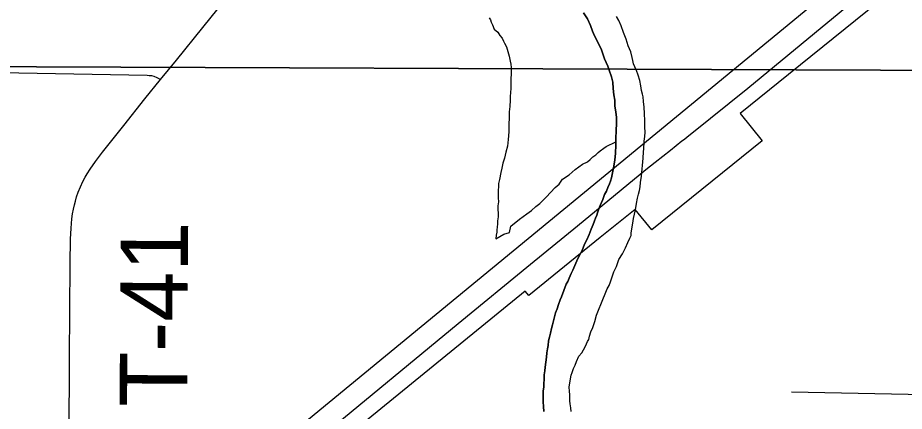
# Model space of a CAD drawing. Extents: x 0 to 34, y 0 to 22.
# Drawn here: x 4.659 to 5.405, y 19.15 to 19.482 of the extents above; entities that cross this region are included whole.
import ezdxf

# ---------------------------------------------------------------- set-up
doc = ezdxf.new("R2010")
doc.units = 0
for name, color, linetype in [('Default', 7, 'Continuous'), ('GM_X_City_Street', 7, 'Continuous'), ('GM_X_Major_River', 7, 'Continuous'), ('GM_X_Minor_River', 7, 'Continuous'), ('GM_X_Section', 7, 'Continuous'), ('GM_X_Township_Road', 7, 'Continuous'), ('GM_X_Township_Road_Text', 7, 'Continuous'), ('GM_X_US_Route', 7, 'Continuous')]:
    doc.layers.add(name, color=color, linetype=linetype)

msp = doc.modelspace()

# ---------------------------------------------------------------- linework, layer by layer
at = {"layer": 'Default'}
msp.add_lwpolyline([(5.44921, 19.54848), (5.30756, 19.4339), (5.26689, 19.40102), (5.28537, 19.37819), (5.19255, 19.3031), (5.1786, 19.32035), (5.14895, 19.29666), (5.08886, 19.24777), (5.08586, 19.25144), (4.91287, 19.11021)], dxfattribs=at)
at = {"layer": 'GM_X_City_Street'}
msp.add_line((5.31011, 19.16656), (5.45108, 19.16403), dxfattribs=at)
at = {"layer": 'GM_X_Major_River'}
for points in [[(5.1383, 19.48087), (5.14081, 19.47511), (5.1426, 19.4705), (5.1444, 19.46666), (5.14982, 19.45551), (5.15123, 19.4513), (5.15264, 19.44708), (5.15409, 19.44401), (5.15553, 19.44093), (5.15658, 19.43749), (5.15872, 19.43212), (5.15975, 19.42754), (5.15999, 19.42221), (5.16062, 19.41688), (5.16126, 19.41231), (5.16152, 19.40737), (5.16215, 19.40241), (5.1628, 19.39784), (5.16268, 19.39291), (5.16251, 19.38645), (5.16236, 19.38038), (5.16222, 19.37469), (5.16204, 19.36748), (5.16152, 19.36217), (5.16063, 19.35688), (5.15935, 19.35122), (5.15849, 19.34706), (5.15765, 19.34404), (5.15683, 19.34179), (5.15562, 19.33878), (5.1544, 19.33577), (5.15281, 19.33277), (5.15118, 19.32864), (5.14916, 19.32375), (5.14755, 19.32), (5.14672, 19.31736), (5.1463, 19.31547), (5.14509, 19.31284), (5.14427, 19.31059), (5.14306, 19.30758), (5.14144, 19.30382), (5.13981, 19.29931), (5.1378, 19.2948), (5.13581, 19.29105), (5.13377, 19.28579), (5.13138, 19.28129), (5.12938, 19.27716), (5.12775, 19.27302), (5.12614, 19.26927), (5.12455, 19.26627), (5.12293, 19.26252), (5.12172, 19.25951), (5.12052, 19.25726), (5.11646, 19.24673), (5.11525, 19.2441), (5.11402, 19.24034), (5.11278, 19.23657), (5.11156, 19.23318), (5.11071, 19.22978), (5.10987, 19.22639), (5.10903, 19.22299), (5.10819, 19.21997), (5.10734, 19.2162), (5.10649, 19.2128), (5.10566, 19.20978), (5.10517, 19.20562), (5.10472, 19.20297), (5.10426, 19.19956), (5.10378, 19.19578), (5.1033, 19.19161), (5.10282, 19.18745), (5.10236, 19.18442), (5.10189, 19.18102), (5.10183, 19.17836), (5.10178, 19.17646), (5.10172, 19.17419), (5.10164, 19.17077), (5.10117, 19.16736), (5.10107, 19.16319), (5.10094, 19.15825), (5.10123, 19.15445), (5.1015, 19.15026)], [(5.1015, 19.15026), (5.10123, 19.15445), (5.10094, 19.15825), (5.10107, 19.16319), (5.10117, 19.16736), (5.10164, 19.17077), (5.10172, 19.17419), (5.10178, 19.17646), (5.10183, 19.17836), (5.10189, 19.18102), (5.10236, 19.18442), (5.10282, 19.18745), (5.1033, 19.19161), (5.10378, 19.19578), (5.10426, 19.19956), (5.10472, 19.20297), (5.10517, 19.20562), (5.10566, 19.20978), (5.10649, 19.2128), (5.10734, 19.2162), (5.10819, 19.21997), (5.10903, 19.22299), (5.10987, 19.22639), (5.11071, 19.22978), (5.11156, 19.23318), (5.11278, 19.23657), (5.11402, 19.24034), (5.11525, 19.2441), (5.11646, 19.24673), (5.12052, 19.25726), (5.12172, 19.25951), (5.12293, 19.26252), (5.12455, 19.26627), (5.12614, 19.26927), (5.12775, 19.27302), (5.12938, 19.27716), (5.13138, 19.28129), (5.13377, 19.28579), (5.13581, 19.29105), (5.1378, 19.2948), (5.13981, 19.29931), (5.14144, 19.30382), (5.14306, 19.30758), (5.14427, 19.31059), (5.14509, 19.31284), (5.1463, 19.31547), (5.14672, 19.31736), (5.14755, 19.32), (5.14916, 19.32375), (5.15118, 19.32864), (5.15281, 19.33277), (5.1544, 19.33577), (5.15562, 19.33878), (5.15683, 19.34179), (5.15765, 19.34404), (5.15849, 19.34706), (5.15935, 19.35122), (5.16063, 19.35688), (5.16152, 19.36217), (5.16204, 19.36748), (5.16222, 19.37469), (5.16236, 19.38038), (5.16251, 19.38645), (5.16268, 19.39291), (5.1628, 19.39784), (5.16215, 19.40241), (5.16152, 19.40737), (5.16126, 19.41231), (5.16062, 19.41688), (5.15999, 19.42221), (5.15975, 19.42754), (5.15872, 19.43212), (5.15658, 19.43749), (5.15553, 19.44093), (5.15409, 19.44401), (5.15264, 19.44708), (5.15123, 19.4513), (5.14982, 19.45551), (5.1444, 19.46666), (5.1426, 19.4705), (5.14081, 19.47511), (5.1383, 19.48087)], [(5.135, 19.48589), (5.1383, 19.48087)], [(5.1383, 19.48087), (5.135, 19.48589)], [(5.16485, 19.47943), (5.16266, 19.48291)], [(5.16485, 19.47943), (5.16266, 19.48291)], [(5.12467, 19.15006), (5.12436, 19.1531), (5.12369, 19.15654), (5.12338, 19.1592), (5.12343, 19.16148), (5.1235, 19.16414), (5.1232, 19.16718), (5.12291, 19.17061), (5.12338, 19.17439), (5.12468, 19.18082), (5.1255, 19.18308), (5.12672, 19.18646), (5.12793, 19.18909), (5.12914, 19.1921), (5.13116, 19.19661), (5.13351, 19.19958), (5.1351, 19.2022), (5.13629, 19.20445), (5.1375, 19.20708), (5.1383, 19.20896), (5.13949, 19.21083), (5.13994, 19.21347), (5.14117, 19.21724), (5.14278, 19.221), (5.14443, 19.22589), (5.14608, 19.23117), (5.14812, 19.23681), (5.14972, 19.24019), (5.15135, 19.24433), (5.15337, 19.24921), (5.15499, 19.25335), (5.15659, 19.25635), (5.1578, 19.25935), (5.15863, 19.26199), (5.15944, 19.26425), (5.16067, 19.26764), (5.16268, 19.27214), (5.16473, 19.27816), (5.16789, 19.28302), (5.17029, 19.2879), (5.17231, 19.2924), (5.17392, 19.29616), (5.17512, 19.29841), (5.17517, 19.30069), (5.17563, 19.30371), (5.17606, 19.3056), (5.17651, 19.30863), (5.177, 19.31279), (5.1787, 19.31997), (5.17959, 19.32526), (5.18046, 19.3298), (5.18131, 19.33319), (5.18214, 19.33621), (5.1826, 19.33923), (5.18307, 19.34302), (5.18397, 19.34831), (5.18511, 19.36348), (5.18562, 19.36878), (5.18569, 19.37144), (5.18574, 19.37333), (5.18616, 19.37522), (5.18623, 19.37788), (5.18671, 19.38166), (5.1868, 19.38546), (5.18653, 19.38964), (5.18666, 19.39496), (5.18643, 19.40104), (5.18618, 19.40636), (5.18555, 19.41131), (5.18527, 19.41512), (5.18457, 19.41741), (5.18388, 19.42047), (5.18322, 19.42428), (5.18257, 19.42886), (5.18117, 19.43345), (5.17975, 19.43728), (5.17831, 19.44036), (5.17723, 19.44304), (5.17654, 19.44572), (5.17585, 19.4484), (5.17482, 19.45298), (5.17267, 19.45797), (5.17091, 19.46371), (5.16878, 19.46946), (5.16664, 19.47483), (5.16485, 19.47943)], [(5.12467, 19.15006), (5.12436, 19.1531), (5.12369, 19.15654), (5.12338, 19.1592), (5.12343, 19.16148), (5.1235, 19.16414), (5.1232, 19.16718), (5.12291, 19.17061), (5.12338, 19.17439), (5.12468, 19.18082), (5.1255, 19.18308), (5.12672, 19.18646), (5.12793, 19.18909), (5.12914, 19.1921), (5.13116, 19.19661), (5.13351, 19.19958), (5.1351, 19.2022), (5.13629, 19.20445), (5.1375, 19.20708), (5.1383, 19.20896), (5.13949, 19.21083), (5.13994, 19.21347), (5.14117, 19.21724), (5.14278, 19.221), (5.14443, 19.22589), (5.14608, 19.23117), (5.14812, 19.23681), (5.14972, 19.24019), (5.15135, 19.24433), (5.15337, 19.24921), (5.15499, 19.25335), (5.15659, 19.25635), (5.1578, 19.25935), (5.15863, 19.26199), (5.15944, 19.26425), (5.16067, 19.26764), (5.16268, 19.27214), (5.16473, 19.27816), (5.16789, 19.28302), (5.17029, 19.2879), (5.17231, 19.2924), (5.17392, 19.29616), (5.17512, 19.29841), (5.17517, 19.30069), (5.17563, 19.30371), (5.17606, 19.3056), (5.17651, 19.30863), (5.177, 19.31279), (5.1787, 19.31997), (5.17959, 19.32526), (5.18046, 19.3298), (5.18131, 19.33319), (5.18214, 19.33621), (5.1826, 19.33923), (5.18307, 19.34302), (5.18397, 19.34831), (5.18511, 19.36348), (5.18562, 19.36878), (5.18569, 19.37144), (5.18574, 19.37333), (5.18616, 19.37522), (5.18623, 19.37788), (5.18671, 19.38166), (5.1868, 19.38546), (5.18653, 19.38964), (5.18666, 19.39496), (5.18643, 19.40104), (5.18618, 19.40636), (5.18555, 19.41131), (5.18527, 19.41512), (5.18457, 19.41741), (5.18388, 19.42047), (5.18322, 19.42428), (5.18257, 19.42886), (5.18117, 19.43345), (5.17975, 19.43728), (5.17831, 19.44036), (5.17723, 19.44304), (5.17654, 19.44572), (5.17585, 19.4484), (5.17482, 19.45298), (5.17267, 19.45797), (5.17091, 19.46371), (5.16878, 19.46946), (5.16664, 19.47483), (5.16485, 19.47943)]]:
    msp.add_lwpolyline(points, dxfattribs=at)
at = {"layer": 'GM_X_Minor_River'}
for points in [[(5.05551, 19.48182), (5.0566, 19.4799), (5.05732, 19.47798), (5.0584, 19.47567), (5.05983, 19.47222), (5.0628, 19.46949), (5.06463, 19.46678), (5.06647, 19.46446), (5.06755, 19.46215), (5.06864, 19.46023), (5.07009, 19.45715), (5.0708, 19.45523), (5.07255, 19.44949), (5.07321, 19.4453), (5.0739, 19.44262), (5.07421, 19.43996), (5.07414, 19.4373), (5.07407, 19.43427), (5.07397, 19.43047), (5.07387, 19.4263), (5.07376, 19.42212), (5.07368, 19.4187), (5.07321, 19.4153), (5.07314, 19.41226), (5.073, 19.40695), (5.07251, 19.4024), (5.07238, 19.39747)], [(5.07238, 19.39747), (5.07225, 19.39216), (5.07209, 19.38571), (5.07155, 19.37926), (5.07102, 19.37358), (5.06976, 19.36868), (5.06849, 19.36339), (5.06724, 19.35924), (5.06638, 19.35509), (5.06553, 19.35131), (5.06424, 19.34565), (5.0634, 19.34225), (5.06332, 19.33922), (5.06325, 19.33656), (5.06318, 19.33352), (5.06309, 19.33011), (5.06339, 19.32668), (5.06292, 19.32328), (5.06285, 19.32024), (5.06315, 19.3172), (5.06307, 19.31416), (5.06261, 19.31075), (5.06254, 19.3081), (5.06247, 19.30544), (5.06203, 19.30317), (5.06199, 19.30127), (5.06154, 19.29863), (5.06109, 19.2956), (5.06802, 19.2996), (5.07262, 19.30101), (5.07389, 19.30629), (5.08126, 19.31218), (5.08744, 19.31658), (5.09132, 19.31952), (5.09482, 19.32285), (5.0983, 19.32542), (5.10103, 19.32801), (5.10376, 19.33098), (5.10727, 19.33469), (5.11117, 19.33877), (5.11467, 19.34172), (5.11743, 19.34582), (5.12284, 19.34948), (5.12789, 19.35391), (5.13408, 19.35831), (5.13831, 19.36048), (5.14063, 19.36232), (5.14297, 19.36454), (5.14529, 19.36638), (5.14724, 19.36823), (5.14918, 19.3697), (5.15227, 19.3719), (5.15421, 19.37337), (5.16228, 19.37721)]]:
    msp.add_lwpolyline(points, dxfattribs=at)
at = {"layer": 'GM_X_Section'}
for points in [[(4.48621, 20.45658), (5.48293, 20.43816), (5.4561, 19.43741), (4.46097, 19.44139)], [(4.46097, 19.44139), (5.4561, 19.43741), (5.43503, 18.42215), (4.43788, 18.43754)]]:
    msp.add_lwpolyline(points, close=True, dxfattribs=at)
at = {"layer": 'GM_X_Township_Road'}
for points in [[(4.77895, 19.42964), (4.79229, 19.44605), (4.81455, 19.47358), (4.85705, 19.52636)], [(4.57393, 19.4372), (4.60683, 19.43632), (4.62859, 19.43581), (4.76778, 19.43331), (4.7695, 19.43318), (4.77144, 19.43298), (4.77325, 19.43258), (4.77578, 19.43153), (4.77695, 19.4309), (4.77895, 19.42964)], [(4.70179, 19.10496), (4.70205, 19.12858), (4.70218, 19.1951), (4.70282, 19.27465), (4.70316, 19.29513), (4.70368, 19.3044), (4.70436, 19.31245), (4.70494, 19.31648), (4.70568, 19.3205), (4.7065, 19.32413), (4.70732, 19.32721), (4.7083, 19.33083), (4.7097, 19.33486), (4.71142, 19.33922), (4.71356, 19.34379), (4.71536, 19.34749), (4.71717, 19.35037), (4.71968, 19.3541), (4.72419, 19.36073), (4.73015, 19.36864), (4.74791, 19.39102), (4.76573, 19.41337), (4.77895, 19.42964)]]:
    msp.add_lwpolyline(points, dxfattribs=at)
at = {"layer": 'GM_X_US_Route'}
for points in [[(3.96494, 18.37191), (4.13878, 18.5144), (4.81337, 19.06963), (5.35068, 19.51206), (5.37928, 19.53639), (5.48648, 19.62254), (5.54106, 19.6666), (5.5871, 19.70508), (5.61899, 19.73138), (5.63905, 19.7465), (5.6887, 19.78794), (5.71796, 19.81226)], [(4.70422, 18.95745), (4.7104, 18.96251), (4.76241, 19.00497), (4.80404, 19.03953), (4.83027, 19.06156), (4.91523, 19.13002), (5.02943, 19.22413), (5.09047, 19.27424), (5.12992, 19.30654), (5.18743, 19.35407), (5.19536, 19.36022), (5.20828, 19.37026), (5.21778, 19.37815), (5.21911, 19.37885), (5.22031, 19.37965), (5.22202, 19.38105), (5.24185, 19.39729), (5.27339, 19.42255), (5.32953, 19.46881), (5.38698, 19.51639), (5.39773, 19.52518)]]:
    msp.add_lwpolyline(points, dxfattribs=at)

# ---------------------------------------------------------------- texts
at = {"layer": 'GM_X_Township_Road_Text'}
msp.add_text('T-41', height=0.056818, rotation=89.64651, dxfattribs=at).set_placement((4.80126, 19.15381))

doc.saveas('drawing.dxf')
